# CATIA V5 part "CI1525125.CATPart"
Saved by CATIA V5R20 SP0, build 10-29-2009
Part number: CI1525125
Bounding box of the stored display mesh (mm): x -24 to 24, y -19.758 to 159.5, z -29.741 to 27.753
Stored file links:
  C:\Users\Raffaele\Desktop\3D X SITO CF\BOLEX\19-INCLINED ASSEMBLY REF_CI\CI1525125.CATPart

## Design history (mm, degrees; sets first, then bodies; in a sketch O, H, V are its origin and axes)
Set1
  DatumSurface1 to DatumSurface16 "MANIFOLD_SOLID_BREP #389"
  DatumSurface17 to DatumSurface39 "MANIFOLD_SOLID_BREP #1134"
Body1 (main body)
